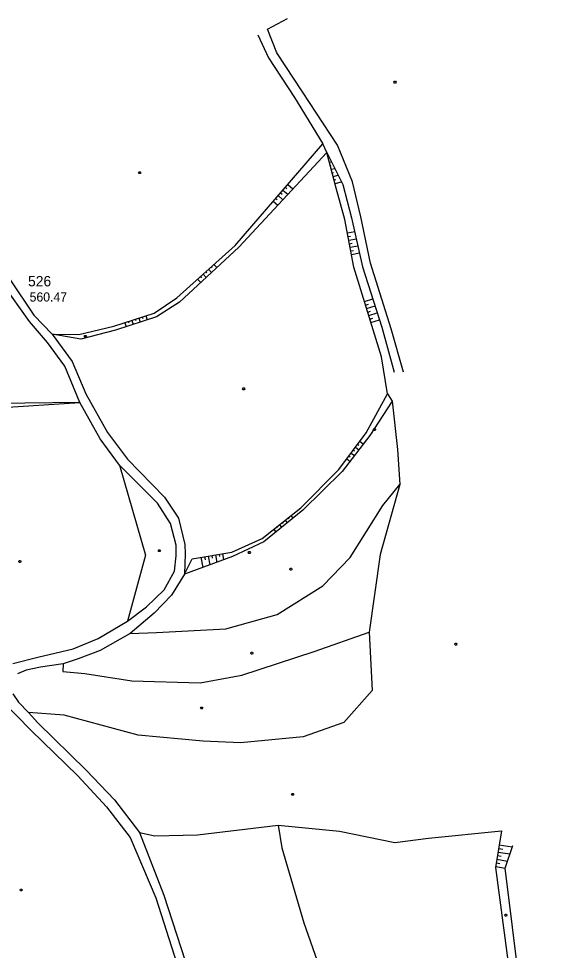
# Model space of a CAD drawing. Extents: x -664960 to -662754, y -993849 to -991145.
# Drawn here: x -662960.5 to -662781.4, y -992369.4 to -992063.8 of the extents above; entities that cross this region are included whole.
import ezdxf

# ---------------------------------------------------------------- set-up
doc = ezdxf.new("R2010")
doc.units = 0
for name, color, linetype in [('Vrstva 1', 7, 'Continuous'), ('Vrstva 13', 7, 'Continuous'), ('Vrstva 27', 7, 'Continuous'), ('Vrstva 63', 7, 'Continuous')]:
    doc.layers.add(name, color=color, linetype=linetype)

msp = doc.modelspace()

# ---------------------------------------------------------------- linework, layer by layer
at = {"layer": 'Vrstva 13'}
for points in [[(-662836.836, -992084.385), (-662836.656, -992084.685), (-662836.836, -992084.985), (-662837.196, -992084.985), (-662837.376, -992084.685), (-662837.196, -992084.385), (-662836.836, -992084.385)], [(-662920.585, -992114.025), (-662920.405, -992114.325), (-662920.585, -992114.625), (-662920.945, -992114.625), (-662921.125, -992114.325), (-662920.945, -992114.025), (-662920.585, -992114.025)], [(-662886.463, -992184.91), (-662886.283, -992185.21), (-662886.463, -992185.51), (-662886.823, -992185.51), (-662887.003, -992185.21), (-662886.823, -992184.91), (-662886.463, -992184.91)], [(-662843.544, -992198.27), (-662843.364, -992198.57), (-662843.544, -992198.87), (-662843.904, -992198.87), (-662844.084, -992198.57), (-662843.904, -992198.27), (-662843.544, -992198.27)], [(-662914.168, -992237.985), (-662913.988, -992238.285), (-662914.168, -992238.585), (-662914.528, -992238.585), (-662914.708, -992238.285), (-662914.528, -992237.985), (-662914.168, -992237.985)], [(-662884.595, -992238.591), (-662884.415, -992238.891), (-662884.595, -992239.191), (-662884.955, -992239.191), (-662885.135, -992238.891), (-662884.955, -992238.591), (-662884.595, -992238.591)], [(-662959.933, -992241.573), (-662959.753, -992241.873), (-662959.933, -992242.173), (-662960.293, -992242.173), (-662960.473, -992241.873), (-662960.293, -992241.573), (-662959.933, -992241.573)], [(-662871.002, -992244.072), (-662870.822, -992244.372), (-662871.002, -992244.672), (-662871.362, -992244.672), (-662871.542, -992244.372), (-662871.362, -992244.072), (-662871.002, -992244.072)], [(-662816.893, -992268.679), (-662816.713, -992268.979), (-662816.893, -992269.279), (-662817.253, -992269.279), (-662817.433, -992268.979), (-662817.253, -992268.679), (-662816.893, -992268.679)], [(-662883.797, -992271.609), (-662883.617, -992271.909), (-662883.797, -992272.209), (-662884.157, -992272.209), (-662884.337, -992271.909), (-662884.157, -992271.609), (-662883.797, -992271.609)], [(-662900.236, -992289.625), (-662900.056, -992289.925), (-662900.236, -992290.225), (-662900.596, -992290.225), (-662900.776, -992289.925), (-662900.596, -992289.625), (-662900.236, -992289.625)], [(-662870.387, -992317.89), (-662870.207, -992318.19), (-662870.387, -992318.49), (-662870.747, -992318.49), (-662870.927, -992318.19), (-662870.747, -992317.89), (-662870.387, -992317.89)], [(-662959.48, -992349.276), (-662959.3, -992349.576), (-662959.48, -992349.876), (-662959.84, -992349.876), (-662960.02, -992349.576), (-662959.84, -992349.276), (-662959.48, -992349.276)], [(-662800.465, -992357.54), (-662800.285, -992357.84), (-662800.465, -992358.14), (-662800.825, -992358.14), (-662801.005, -992357.84), (-662800.825, -992357.54), (-662800.465, -992357.54)]]:
    msp.add_lwpolyline(points, dxfattribs=at)
at = {"layer": 'Vrstva 27'}
for points in [[(-662882.07, -992069.19), (-662878.5, -992076.67), (-662870.02, -992089.69), (-662860.7, -992104.92)], [(-662834.25, -992179.78), (-662838.29, -992165.56), (-662845.07, -992143.98), (-662848.21, -992128.8), (-662850.93, -992117.32), (-662855.83, -992105.29), (-662867.39, -992087.87), (-662875.79, -992075.06), (-662878.86, -992067.27)], [(-662963.51, -992149.14), (-662955.49, -992161.05), (-662949.49, -992167.25), (-662942.9, -992176.29), (-662938.47, -992186.84), (-662931.39, -992199.59), (-662924.74, -992208.32), (-662912.6, -992220.79), (-662908.05, -992227.67), (-662906.01, -992236.25), (-662905.81, -992239.38), (-662906.06, -992245.99), (-662910.37, -992252.95), (-662915.98, -992258.82), (-662923.87, -992265.49), (-662933.7, -992271.05), (-662940.93, -992273.77), (-662945.92, -992275.38), (-662953.33, -992276.47), (-662958.04, -992277.5), (-662960.9, -992278.71)], [(-662962.4, -992275.33), (-662954.24, -992273.28), (-662942.59, -992270.5), (-662934.44, -992267.16), (-662924.78, -992261.37), (-662918.54, -992256.77), (-662912.72, -992251.15), (-662909.39, -992245.07), (-662908.76, -992239.95), (-662908.85, -992236.47), (-662910.64, -992229.36), (-662914.97, -992222.7), (-662927.44, -992210.22), (-662933.8, -992201.59), (-662940.46, -992189.74), (-662945.38, -992177.82), (-662951.05, -992170.03), (-662956.94, -992163.1), (-662965.75, -992150.64)], [(-662962.44, -992285.29), (-662960.53, -992287.98), (-662957.278, -992291.341), (-662954.15, -992294.72), (-662938.36, -992310.24), (-662929.08, -992320.03), (-662920.86, -992330.7), (-662912.84, -992351.32), (-662905.9, -992372.83), (-662896.75, -992402.99), (-662892.28, -992419.6), (-662886.17, -992439.46), (-662883.07, -992447.93), (-662879.65, -992454.82), (-662876.1, -992460.53), (-662867.14, -992470.96), (-662855.91, -992480.61), (-662847.69, -992487.2), (-662824.02, -992504.16), (-662808.83, -992512.81)], [(-662963.5, -992290.01), (-662961.05, -992292.51), (-662956.54, -992297.17), (-662941.08, -992312.11), (-662931.7, -992322.28), (-662923.87, -992332.38), (-662915.46, -992352.13), (-662908.55, -992373.66)]]:
    msp.add_lwpolyline(points, dxfattribs=at)
at = {"layer": 'Vrstva 63'}
for p, q in [((-662878.86, -992067.27), (-662872.27, -992063.83)), ((-662858.556, -992110.924), (-662857.879, -992110.743)), ((-662858.247, -992112.084), (-662857.939, -992112.002)), ((-662857.937, -992113.243), (-662856.768, -992112.931)), ((-662857.627, -992114.402), (-662857.156, -992114.277)), ((-662857.317, -992115.562), (-662855.656, -992115.118)), ((-662872.221, -992118.23), (-662870.538, -992119.687)), ((-662857.007, -992116.721), (-662856.372, -992116.551)), ((-662856.697, -992117.88), (-662854.545, -992117.305)), ((-662875.363, -992121.859), (-662873.811, -992123.202)), ((-662874.577, -992120.952), (-662874.05, -992121.409)), ((-662873.792, -992120.044), (-662872.175, -992121.444)), ((-662873.006, -992119.137), (-662872.457, -992119.613)), ((-662876.933, -992123.674), (-662875.447, -992124.96)), ((-662876.148, -992122.766), (-662875.642, -992123.204)), ((-662852.607, -992134.099), (-662850.223, -992133.646)), ((-662852.383, -992135.278), (-662851.576, -992135.125)), ((-662852.16, -992136.457), (-662849.696, -992135.989)), ((-662851.936, -992137.636), (-662851.102, -992137.478)), ((-662851.712, -992138.815), (-662849.169, -992138.332)), ((-662851.488, -992139.994), (-662850.628, -992139.831)), ((-662851.265, -992141.173), (-662848.643, -992140.675)), ((-662898.201, -992146.016), (-662897.236, -992147.089)), ((-662897.309, -992145.214), (-662896.992, -992145.566)), ((-662896.417, -992144.411), (-662895.479, -992145.453)), ((-662901.769, -992149.227), (-662900.75, -992150.36)), ((-662900.877, -992148.424), (-662900.542, -992148.796)), ((-662899.985, -992147.622), (-662898.993, -992148.724)), ((-662899.093, -992146.819), (-662898.767, -992147.181)), ((-662847.017, -992156.609), (-662844.285, -992155.77)), ((-662846.665, -992157.756), (-662845.752, -992157.476)), ((-662846.313, -992158.903), (-662843.562, -992158.059)), ((-662919.946, -992161.677), (-662919.8, -992162.123)), ((-662918.805, -992161.305), (-662918.369, -992162.64)), ((-662845.961, -992160.05), (-662845.042, -992159.768)), ((-662845.609, -992161.198), (-662842.839, -992160.347)), ((-662925.65, -992163.538), (-662925.208, -992164.891)), ((-662924.509, -992163.166), (-662924.362, -992163.616)), ((-662923.368, -992162.794), (-662922.929, -992164.14)), ((-662922.227, -992162.422), (-662922.081, -992162.869)), ((-662921.086, -992162.05), (-662920.649, -992163.39)), ((-662845.257, -992162.345), (-662844.331, -992162.061)), ((-662844.905, -992163.492), (-662842.116, -992162.636)), ((-662940.46, -992189.74), (-662978.64, -992190.16)), ((-662978.36, -992192.16), (-662940.46, -992189.74)), ((-662849.987, -992204.361), (-662848.823, -992205.23)), ((-662849.269, -992203.4), (-662848.878, -992203.692)), ((-662848.551, -992202.438), (-662847.364, -992203.324)), ((-662852.14, -992207.246), (-662851.764, -992207.527)), ((-662851.422, -992206.285), (-662850.281, -992207.137)), ((-662850.705, -992205.323), (-662850.321, -992205.609)), ((-662852.858, -992208.208), (-662851.739, -992209.043)), ((-662873.99, -992229.027), (-662873.756, -992229.323)), ((-662873.049, -992228.282), (-662872.355, -992229.159)), ((-662872.109, -992227.537), (-662871.881, -992227.825)), ((-662871.168, -992226.792), (-662870.492, -992227.645)), ((-662876.812, -992231.262), (-662876.082, -992232.185)), ((-662875.872, -992230.517), (-662875.631, -992230.821)), ((-662874.931, -992229.772), (-662874.218, -992230.672)), ((-662900.669, -992240.461), (-662900.108, -992243.81)), ((-662899.485, -992240.263), (-662899.311, -992241.304)), ((-662898.302, -992240.065), (-662897.815, -992242.97)), ((-662897.118, -992239.866), (-662896.968, -992240.76)), ((-662895.935, -992239.668), (-662895.522, -992242.131)), ((-662894.751, -992239.47), (-662894.626, -992240.216)), ((-662893.568, -992239.272), (-662893.229, -992241.291)), ((-662802.988, -992335.954), (-662801.641, -992336.174)), ((-662802.795, -992334.77), (-662798.562, -992335.459)), ((-662803.373, -992338.323), (-662802.154, -992338.522)), ((-662803.18, -992337.139), (-662799.328, -992337.766)), ((-662803.952, -992341.876), (-662800.86, -992342.38)), ((-662803.759, -992340.692), (-662802.666, -992340.87)), ((-662803.566, -992339.507), (-662800.094, -992340.073))]:
    msp.add_line(p, q, dxfattribs=at)
for points in [[(-662949.49, -992167.25), (-662940.79, -992167.45), (-662929.21, -992164.7), (-662916, -992160.39), (-662908.62, -992155.39), (-662889.49, -992138.18), (-662860.7, -992104.92)], [(-662839.49, -992186.88), (-662841.44, -992174.78), (-662850.47, -992145.36), (-662853.44, -992129.71), (-662856.27, -992119.48), (-662859.41, -992107.73), (-662860.7, -992104.92)], [(-662859.41, -992107.73), (-662888.3, -992138.77), (-662907.7, -992156.83), (-662915.21, -992161.6), (-662928.7, -992166.04), (-662940.12, -992168.91), (-662949.49, -992167.25)], [(-662859.41, -992107.73), (-662854.08, -992118.22), (-662851.24, -992129.12), (-662847.63, -992145.18), (-662841.35, -992165.06), (-662837.32, -992179.75)], [(-662938.41, -992167.74), (-662938.23, -992168.04), (-662938.41, -992168.34), (-662938.77, -992168.34), (-662938.95, -992168.04), (-662938.77, -992167.74), (-662938.41, -992167.74)], [(-662906.06, -992245.99), (-662903.53, -992240.94), (-662890.57, -992238.77), (-662880.61, -992234.27), (-662867.92, -992224.22), (-662855.42, -992211.64), (-662846.47, -992199.65), (-662839.49, -992186.88)], [(-662839.49, -992186.88), (-662837.89, -992189.33), (-662836.18, -992205.11), (-662835.42, -992216.56), (-662841.89, -992239.55), (-662845.511, -992265.058), (-662844.51, -992284.16)], [(-662837.89, -992189.33), (-662845.25, -992200.56), (-662854.3, -992212.39), (-662867.26, -992225.02), (-662880.04, -992235.4), (-662890.36, -992240.24), (-662906.06, -992245.99)], [(-662927.44, -992210.22), (-662918.92, -992239.75), (-662924.78, -992261.37)], [(-662923.87, -992265.49), (-662915.3, -992265.17), (-662892.53, -992263.96), (-662875.72, -992259.2), (-662860.71, -992249.79), (-662851.71, -992240.58), (-662841.03, -992223.44), (-662835.42, -992216.56)], [(-662945.92, -992275.38), (-662945.98, -992277.93), (-662938.74, -992278.57), (-662923.36, -992280.94), (-662900.97, -992281.66), (-662887.3, -992279.09), (-662863.57, -992271.37), (-662845.46, -992265.04)], [(-662844.51, -992284.16), (-662853.79, -992294.62), (-662867.1, -992299.38), (-662887.73, -992301.31), (-662899.94, -992300.77), (-662921.33, -992298.83), (-662945.55, -992292.25), (-662957.278, -992291.341)], [(-662920.86, -992330.7), (-662915.82, -992331.81), (-662901.79, -992331.44), (-662875.36, -992328.35), (-662855.22, -992330.34), (-662837.03, -992333.96), (-662826.03, -992332.56), (-662802.05, -992330.2)], [(-662875.36, -992328.35), (-662874.09, -992335.77), (-662866.97, -992360.3), (-662855.48, -992393.08), (-662845.48, -992417.13), (-662835.18, -992439.2), (-662821.14, -992468.7), (-662855.91, -992480.61)], [(-662802.05, -992330.2), (-662804.01, -992342.23), (-662798.82, -992381.76), (-662794.5, -992408.18), (-662790.74, -992432.32), (-662786.61, -992472.35), (-662783.31, -992500.5), (-662784.14, -992514.14), (-662785.07, -992524.38), (-662785.85, -992525.39), (-662786.66, -992524.94), (-662790.13, -992521.76), (-662795.67, -992517.55), (-662802.72, -992514.39), (-662808.83, -992512.81), (-662803.49, -992515.44), (-662801, -992517.02), (-662795.02, -992519.93), (-662787.99, -992526.89)], [(-662785.01, -992529.04), (-662783.31, -992523.58), (-662782.47, -992513.69), (-662781.44, -992499.41), (-662784.74, -992472.03), (-662788.36, -992430.9), (-662792.77, -992407.14), (-662796, -992381.1), (-662800.86, -992342.38), (-662798.39, -992334.94)]]:
    msp.add_lwpolyline(points, dxfattribs=at)

# ---------------------------------------------------------------- texts
at = {"layer": 'Vrstva 1'}
msp.add_text('526', height=3.4, dxfattribs=at).set_placement((-662957.411, -992151.628))
at = {"layer": 'Vrstva 63'}
msp.add_text('560.47', height=3, dxfattribs=at).set_placement((-662956.887, -992156.608))

doc.saveas('drawing.dxf')
